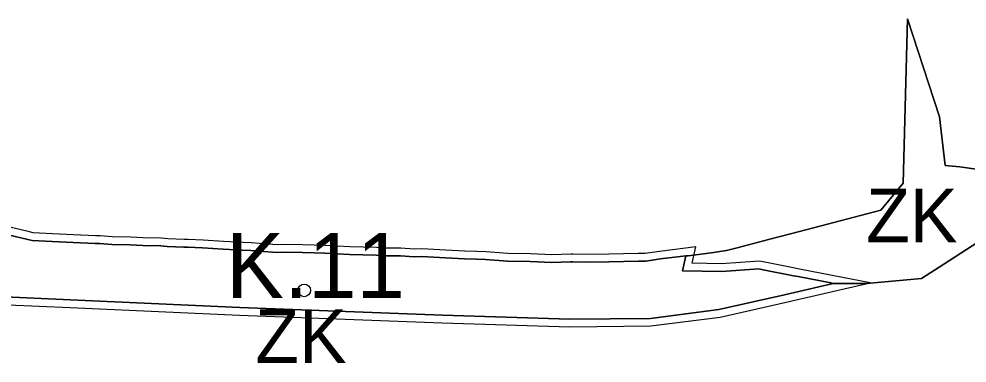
# Model space of a CAD drawing. Extents: x -555509 to -553005, y -1186756 to -1182560.
# Drawn here: x -555081.4 to -554833.4, y -1186291.9 to -1186202.1 of the extents above; entities that cross this region are included whole.
import ezdxf

# ---------------------------------------------------------------- set-up
doc = ezdxf.new("R2010")
doc.units = 0
for name, color, linetype in [('Level 46', 7, 'Continuous'), ('Level 56', 7, 'Continuous'), ('Level 59', 7, 'Continuous'), ('Level 63', 7, 'Continuous'), ('navrh_ZK', 7, 'Continuous'), ('OBRYS_PLOCH', 7, 'Continuous'), ('stav_AP', 7, 'Continuous'), ('stav_ZK', 7, 'Continuous')]:
    doc.layers.add(name, color=color, linetype=linetype)

msp = doc.modelspace()

# ---------------------------------------------------------------- linework, layer by layer
at = {"layer": 'Level 46'}
msp.add_circle((-555006.78, -1186272.95), 1.64, dxfattribs=at)
at = {"layer": 'Level 56'}
msp.add_lwpolyline([(-555092.41, -1186276.35), (-555068.02, -1186277.38), (-555023.74, -1186279.43), (-554970.68, -1186281.4), (-554937.3, -1186282.48), (-554916.11, -1186282.25), (-554897.96, -1186279.95), (-554880.77, -1186276.05), (-554858.76, -1186270.94), (-554868.68, -1186269.05), (-554877.26, -1186267.4), (-554878.46, -1186267.16), (-554886.36, -1186265.6), (-554887.72, -1186265.29), (-554897.64, -1186266.01), (-554905.34, -1186265.88), (-554904.39, -1186261.61), (-554913.89, -1186262.77), (-554917.63, -1186263.28), (-554919.43, -1186263.33), (-554927.14, -1186263.47), (-554932.26, -1186263.55), (-554936.49, -1186263.5), (-554937.09, -1186263.47), (-554942.03, -1186263.63), (-554947.61, -1186263.42), (-554953.57, -1186263.32), (-554959.24, -1186262.92), (-554961.6, -1186262.81), (-554964.74, -1186262.67), (-554969.75, -1186262.42), (-554976.05, -1186262.1), (-554978.04, -1186262.16), (-554981.52, -1186261.95), (-554986.17, -1186261.91), (-554987.88, -1186261.78), (-554994.82, -1186261.58), (-555001.28, -1186261.21), (-555004.17, -1186261.18), (-555007.2, -1186261.05), (-555012.39, -1186260.95), (-555013.86, -1186261.01), (-555018.52, -1186260.69), (-555020.66, -1186260.57), (-555022.78, -1186260.45), (-555027.86, -1186260.21), (-555033.24, -1186259.86), (-555037.13, -1186259.67), (-555038.17, -1186259.63), (-555042.48, -1186259.45), (-555045.1, -1186259.2), (-555047.35, -1186259.3), (-555052.24, -1186259.05), (-555057.03, -1186258.95), (-555060.12, -1186258.69), (-555061.37, -1186258.68), (-555067.15, -1186258.4), (-555072.6, -1186258.16), (-555077.64, -1186257.95), (-555078.59, -1186257.68), (-555085.64, -1186256)], dxfattribs=at)
at = {"layer": 'navrh_ZK'}
for p, q in [((-554907.83, -1186267.84), (-554906.96, -1186263.94)), ((-554897.58, -1186268.01), (-554907.83, -1186267.84)), ((-554887.87, -1186267.31), (-554897.58, -1186268.01)), ((-554886.77, -1186267.56), (-554887.87, -1186267.31)), ((-554878.85, -1186269.12), (-554886.77, -1186267.56)), ((-554877.64, -1186269.36), (-554878.85, -1186269.12)), ((-554869.06, -1186271.01), (-554877.64, -1186269.36)), ((-554868.43, -1186271.13), (-554869.06, -1186271.01)), ((-555089.85, -1186274.46), (-555067.93, -1186275.38))]:
    msp.add_line(p, q, dxfattribs=at)
for points in [[(-554906.96, -1186263.94), (-554913.63, -1186264.75), (-554917.47, -1186265.28), (-554919.39, -1186265.33), (-554927.11, -1186265.47), (-554932.26, -1186265.55), (-554936.56, -1186265.5), (-554937.11, -1186265.47), (-554942.03, -1186265.63), (-554947.66, -1186265.42), (-554953.66, -1186265.32), (-554959.36, -1186264.92), (-554961.69, -1186264.81), (-554964.83, -1186264.67), (-554969.85, -1186264.42), (-554976.07, -1186264.1), (-554978.07, -1186264.16), (-554981.59, -1186263.95), (-554986.25, -1186263.91), (-554987.98, -1186263.78), (-554994.91, -1186263.58), (-555001.35, -1186263.21), (-555004.22, -1186263.18), (-555007.26, -1186263.05), (-555012.37, -1186262.95), (-555013.89, -1186263.01), (-555018.64, -1186262.69), (-555020.77, -1186262.57), (-555022.88, -1186262.45), (-555027.97, -1186262.21), (-555033.35, -1186261.86), (-555037.22, -1186261.67), (-555038.25, -1186261.63), (-555042.62, -1186261.45), (-555045.15, -1186261.2), (-555047.35, -1186261.3), (-555052.31, -1186261.05), (-555057.13, -1186260.95), (-555060.21, -1186260.69), (-555061.43, -1186260.68), (-555067.24, -1186260.4), (-555072.69, -1186260.16), (-555077.96, -1186259.94), (-555079.09, -1186259.62), (-555084.2, -1186258.4)], [(-554937.28, -1186280.48), (-554916.25, -1186280.25), (-554898.31, -1186277.98), (-554881.21, -1186274.1), (-554868.43, -1186271.13)], [(-555067.93, -1186275.38), (-555023.66, -1186277.43), (-554970.61, -1186279.4), (-554937.28, -1186280.48)]]:
    msp.add_lwpolyline(points, dxfattribs=at)
at = {"layer": 'OBRYS_PLOCH'}
for p, q in [((-554849, -1186202.06), (-554850.12, -1186244.95)), ((-554850.12, -1186244.95), (-554849, -1186202.06)), ((-554840.62, -1186227.66), (-554849, -1186202.06)), ((-554849, -1186202.06), (-554840.62, -1186227.66)), ((-554839.16, -1186240.36), (-554840.62, -1186227.66)), ((-554840.62, -1186227.66), (-554839.16, -1186240.36)), ((-554835.28, -1186240.65), (-554839.16, -1186240.36)), ((-554839.16, -1186240.36), (-554835.28, -1186240.65)), ((-554830.46, -1186241.38), (-554835.28, -1186240.65)), ((-554835.28, -1186240.65), (-554830.46, -1186241.38)), ((-554850.12, -1186244.95), (-554855.96, -1186252.02)), ((-554855.96, -1186252.02), (-554850.12, -1186244.95)), ((-554855.96, -1186252.02), (-554869.97, -1186255.68)), ((-554869.97, -1186255.68), (-554855.96, -1186252.02)), ((-554869.97, -1186255.68), (-554877.27, -1186257.56)), ((-554877.27, -1186257.56), (-554869.97, -1186255.68)), ((-555079.09, -1186259.62), (-555084.2, -1186258.4)), ((-555084.2, -1186258.4), (-555079.09, -1186259.62)), ((-554877.27, -1186257.56), (-554885.02, -1186259.59)), ((-554885.02, -1186259.59), (-554877.27, -1186257.56)), ((-555077.96, -1186259.94), (-555079.09, -1186259.62)), ((-555079.09, -1186259.62), (-555077.96, -1186259.94)), ((-555072.69, -1186260.16), (-555077.96, -1186259.94)), ((-555077.96, -1186259.94), (-555072.69, -1186260.16)), ((-555067.24, -1186260.4), (-555072.69, -1186260.16)), ((-555061.43, -1186260.68), (-555067.24, -1186260.4)), ((-555060.21, -1186260.69), (-555061.43, -1186260.68)), ((-555061.43, -1186260.68), (-555060.21, -1186260.69)), ((-555060.21, -1186260.69), (-555057.13, -1186260.95)), ((-554885.02, -1186259.59), (-554893.59, -1186261.84)), ((-554893.59, -1186261.84), (-554885.02, -1186259.59)), ((-554839.51, -1186266.06), (-554829.17, -1186259.42)), ((-554829.17, -1186259.42), (-554839.51, -1186266.06)), ((-555045.15, -1186261.2), (-555047.35, -1186261.3)), ((-555047.35, -1186261.3), (-555045.15, -1186261.2)), ((-555045.15, -1186261.2), (-555042.62, -1186261.45)), ((-555042.62, -1186261.45), (-555038.25, -1186261.63)), ((-555038.25, -1186261.63), (-555037.22, -1186261.67)), ((-555037.22, -1186261.67), (-555033.35, -1186261.86)), ((-555022.88, -1186262.45), (-555027.97, -1186262.21)), ((-555020.77, -1186262.57), (-555022.88, -1186262.45)), ((-555022.88, -1186262.45), (-555020.77, -1186262.57)), ((-555018.64, -1186262.69), (-555020.77, -1186262.57)), ((-555020.77, -1186262.57), (-555018.64, -1186262.69)), ((-555013.89, -1186263.01), (-555018.64, -1186262.69)), ((-555018.64, -1186262.69), (-555013.89, -1186263.01)), ((-555012.37, -1186262.95), (-555013.89, -1186263.01)), ((-555013.89, -1186263.01), (-555012.37, -1186262.95)), ((-555007.26, -1186263.05), (-555012.37, -1186262.95)), ((-555012.37, -1186262.95), (-555007.26, -1186263.05)), ((-555007.26, -1186263.05), (-555004.22, -1186263.18)), ((-555004.22, -1186263.18), (-555001.35, -1186263.21)), ((-554994.91, -1186263.58), (-555001.35, -1186263.21)), ((-554900.36, -1186263.12), (-554906.34, -1186263.88)), ((-554906.34, -1186263.88), (-554900.36, -1186263.12)), ((-554896.34, -1186262.51), (-554900.36, -1186263.12)), ((-554900.36, -1186263.12), (-554896.34, -1186262.51)), ((-554893.59, -1186261.84), (-554896.34, -1186262.51)), ((-554896.34, -1186262.51), (-554893.59, -1186261.84)), ((-554987.98, -1186263.78), (-554994.91, -1186263.58)), ((-554986.25, -1186263.91), (-554987.98, -1186263.78)), ((-554987.98, -1186263.78), (-554986.25, -1186263.91)), ((-554981.59, -1186263.95), (-554986.25, -1186263.91)), ((-554986.25, -1186263.91), (-554981.59, -1186263.95)), ((-554981.59, -1186263.95), (-554978.07, -1186264.16)), ((-554978.07, -1186264.16), (-554976.07, -1186264.1)), ((-554976.07, -1186264.1), (-554969.85, -1186264.42)), ((-554969.85, -1186264.42), (-554964.83, -1186264.67)), ((-554961.69, -1186264.81), (-554964.83, -1186264.67)), ((-554964.83, -1186264.67), (-554961.69, -1186264.81)), ((-554959.36, -1186264.92), (-554961.69, -1186264.81)), ((-554961.69, -1186264.81), (-554959.36, -1186264.92)), ((-554953.66, -1186265.32), (-554959.36, -1186264.92)), ((-554947.66, -1186265.42), (-554953.66, -1186265.32)), ((-554942.03, -1186265.63), (-554947.66, -1186265.42)), ((-554947.66, -1186265.42), (-554942.03, -1186265.63)), ((-554937.11, -1186265.47), (-554942.03, -1186265.63)), ((-554942.03, -1186265.63), (-554937.11, -1186265.47)), ((-554936.56, -1186265.5), (-554937.11, -1186265.47)), ((-554937.11, -1186265.47), (-554936.56, -1186265.5)), ((-554919.39, -1186265.33), (-554927.11, -1186265.47)), ((-554927.11, -1186265.47), (-554919.39, -1186265.33)), ((-554917.47, -1186265.28), (-554919.39, -1186265.33)), ((-554919.39, -1186265.33), (-554917.47, -1186265.28)), ((-554913.63, -1186264.75), (-554917.47, -1186265.28)), ((-554906.96, -1186263.94), (-554913.63, -1186264.75)), ((-554906.96, -1186263.94), (-554907.83, -1186267.84)), ((-554907.83, -1186267.84), (-554906.96, -1186263.94)), ((-554907.83, -1186267.84), (-554906.96, -1186263.94)), ((-554906.34, -1186263.88), (-554906.96, -1186263.94)), ((-554906.96, -1186263.94), (-554906.34, -1186263.88)), ((-554907.83, -1186267.84), (-554897.58, -1186268.01)), ((-554897.58, -1186268.01), (-554907.83, -1186267.84)), ((-554897.58, -1186268.01), (-554907.83, -1186267.84)), ((-554897.58, -1186268.01), (-554887.87, -1186267.31)), ((-554887.87, -1186267.31), (-554897.58, -1186268.01)), ((-554887.87, -1186267.31), (-554897.58, -1186268.01)), ((-554887.87, -1186267.31), (-554886.77, -1186267.56)), ((-554886.77, -1186267.56), (-554887.87, -1186267.31)), ((-554886.77, -1186267.56), (-554887.87, -1186267.31)), ((-554886.77, -1186267.56), (-554878.85, -1186269.12)), ((-554878.85, -1186269.12), (-554886.77, -1186267.56)), ((-554878.85, -1186269.12), (-554886.77, -1186267.56)), ((-554845.34, -1186269.8), (-554839.51, -1186266.06)), ((-554839.51, -1186266.06), (-554845.34, -1186269.8)), ((-554878.85, -1186269.12), (-554877.64, -1186269.36)), ((-554877.64, -1186269.36), (-554878.85, -1186269.12)), ((-554877.64, -1186269.36), (-554878.85, -1186269.12)), ((-554877.64, -1186269.36), (-554869.06, -1186271.01)), ((-554869.06, -1186271.01), (-554877.64, -1186269.36)), ((-554869.06, -1186271.01), (-554877.64, -1186269.36)), ((-554859.71, -1186271.15), (-554845.34, -1186269.8)), ((-554845.34, -1186269.8), (-554859.71, -1186271.15)), ((-554869.06, -1186271.01), (-554868.43, -1186271.13)), ((-554868.43, -1186271.13), (-554869.06, -1186271.01)), ((-554868.43, -1186271.13), (-554869.06, -1186271.01)), ((-554868.43, -1186271.13), (-554860.32, -1186271.15)), ((-554860.32, -1186271.15), (-554868.43, -1186271.13)), ((-554860.32, -1186271.15), (-554859.71, -1186271.15)), ((-554859.71, -1186271.15), (-554860.32, -1186271.15)), ((-555089.85, -1186274.46), (-555067.93, -1186275.38)), ((-555089.85, -1186274.46), (-555067.93, -1186275.38)), ((-555067.93, -1186275.38), (-555089.85, -1186274.46)), ((-555067.93, -1186275.38), (-555023.66, -1186277.43)), ((-555023.66, -1186277.43), (-555067.93, -1186275.38)), ((-555023.66, -1186277.43), (-554970.61, -1186279.4)), ((-554970.61, -1186279.4), (-555023.66, -1186277.43)), ((-554898.31, -1186277.98), (-554916.25, -1186280.25)), ((-554970.61, -1186279.4), (-554937.28, -1186280.48)), ((-554937.28, -1186280.48), (-554970.61, -1186279.4)), ((-554916.25, -1186280.25), (-554937.28, -1186280.48))]:
    msp.add_line(p, q, dxfattribs=at)
for points in [[(-554906.96, -1186263.94), (-554913.63, -1186264.75), (-554917.47, -1186265.28), (-554919.39, -1186265.33), (-554927.11, -1186265.47), (-554932.26, -1186265.55), (-554936.56, -1186265.5), (-554937.11, -1186265.47), (-554942.03, -1186265.63), (-554947.66, -1186265.42), (-554953.66, -1186265.32), (-554959.36, -1186264.92), (-554961.69, -1186264.81), (-554964.83, -1186264.67), (-554969.85, -1186264.42), (-554976.07, -1186264.1), (-554978.07, -1186264.16), (-554981.59, -1186263.95), (-554986.25, -1186263.91), (-554987.98, -1186263.78), (-554994.91, -1186263.58), (-555001.35, -1186263.21), (-555004.22, -1186263.18), (-555007.26, -1186263.05), (-555012.37, -1186262.95), (-555013.89, -1186263.01), (-555018.64, -1186262.69), (-555020.77, -1186262.57), (-555022.88, -1186262.45), (-555027.97, -1186262.21), (-555033.35, -1186261.86), (-555037.22, -1186261.67), (-555038.25, -1186261.63), (-555042.62, -1186261.45), (-555045.15, -1186261.2), (-555047.35, -1186261.3), (-555052.31, -1186261.05), (-555057.13, -1186260.95), (-555060.21, -1186260.69), (-555061.43, -1186260.68), (-555067.24, -1186260.4), (-555072.69, -1186260.16), (-555077.96, -1186259.94), (-555079.09, -1186259.62), (-555084.2, -1186258.4)], [(-555072.69, -1186260.16), (-555067.24, -1186260.4), (-555061.43, -1186260.68)], [(-555047.35, -1186261.3), (-555052.31, -1186261.05), (-555057.13, -1186260.95), (-555060.21, -1186260.69)], [(-555057.13, -1186260.95), (-555052.31, -1186261.05), (-555047.35, -1186261.3)], [(-555038.25, -1186261.63), (-555042.62, -1186261.45), (-555045.15, -1186261.2)], [(-555027.97, -1186262.21), (-555033.35, -1186261.86), (-555037.22, -1186261.67), (-555038.25, -1186261.63)], [(-555033.35, -1186261.86), (-555027.97, -1186262.21), (-555022.88, -1186262.45)], [(-555001.35, -1186263.21), (-555004.22, -1186263.18), (-555007.26, -1186263.05)], [(-555001.35, -1186263.21), (-554994.91, -1186263.58), (-554987.98, -1186263.78)], [(-554964.83, -1186264.67), (-554969.85, -1186264.42), (-554976.07, -1186264.1), (-554978.07, -1186264.16), (-554981.59, -1186263.95)], [(-554959.36, -1186264.92), (-554953.66, -1186265.32), (-554947.66, -1186265.42)], [(-554927.11, -1186265.47), (-554932.26, -1186265.55), (-554936.56, -1186265.5)], [(-554936.56, -1186265.5), (-554932.26, -1186265.55), (-554927.11, -1186265.47)], [(-554917.47, -1186265.28), (-554913.63, -1186264.75), (-554906.96, -1186263.94)], [(-554937.28, -1186280.48), (-554916.25, -1186280.25), (-554898.31, -1186277.98), (-554881.21, -1186274.1), (-554868.43, -1186271.13)], [(-554937.28, -1186280.48), (-554916.25, -1186280.25), (-554898.31, -1186277.98), (-554881.21, -1186274.1), (-554868.43, -1186271.13)], [(-554868.43, -1186271.13), (-554881.21, -1186274.1), (-554898.31, -1186277.98)], [(-555067.93, -1186275.38), (-555023.66, -1186277.43), (-554970.61, -1186279.4), (-554937.28, -1186280.48)]]:
    msp.add_lwpolyline(points, dxfattribs=at)
at = {"layer": 'stav_AP'}
for p, q in [((-554850.12, -1186244.95), (-554849, -1186202.06)), ((-554849, -1186202.06), (-554840.62, -1186227.66)), ((-554840.62, -1186227.66), (-554839.16, -1186240.36)), ((-554839.16, -1186240.36), (-554835.28, -1186240.65)), ((-554835.28, -1186240.65), (-554830.46, -1186241.38)), ((-554855.96, -1186252.02), (-554850.12, -1186244.95)), ((-554869.97, -1186255.68), (-554855.96, -1186252.02)), ((-554877.27, -1186257.56), (-554869.97, -1186255.68)), ((-554885.02, -1186259.59), (-554877.27, -1186257.56)), ((-555077.96, -1186259.94), (-555072.69, -1186260.16)), ((-555072.69, -1186260.16), (-555067.24, -1186260.4)), ((-554893.59, -1186261.84), (-554885.02, -1186259.59)), ((-554829.17, -1186259.42), (-554839.51, -1186266.06)), ((-555052.31, -1186261.05), (-555047.35, -1186261.3)), ((-555047.35, -1186261.3), (-555045.15, -1186261.2)), ((-555037.22, -1186261.67), (-555033.35, -1186261.86)), ((-555020.77, -1186262.57), (-555018.64, -1186262.69)), ((-555004.22, -1186263.18), (-555001.35, -1186263.21)), ((-555001.35, -1186263.21), (-554994.91, -1186263.58)), ((-554900.36, -1186263.12), (-554896.34, -1186262.51)), ((-554896.34, -1186262.51), (-554893.59, -1186261.84)), ((-554986.25, -1186263.91), (-554981.59, -1186263.95)), ((-554976.07, -1186264.1), (-554969.85, -1186264.42)), ((-554961.69, -1186264.81), (-554959.36, -1186264.92)), ((-554959.36, -1186264.92), (-554953.66, -1186265.32)), ((-554942.03, -1186265.63), (-554937.11, -1186265.47)), ((-554937.11, -1186265.47), (-554936.56, -1186265.5)), ((-554936.56, -1186265.5), (-554932.26, -1186265.55)), ((-554932.26, -1186265.55), (-554927.11, -1186265.47)), ((-554927.11, -1186265.47), (-554919.39, -1186265.33)), ((-554919.39, -1186265.33), (-554917.47, -1186265.28)), ((-554917.47, -1186265.28), (-554913.63, -1186264.75)), ((-554913.63, -1186264.75), (-554906.96, -1186263.94)), ((-554839.51, -1186266.06), (-554845.34, -1186269.8)), ((-554845.34, -1186269.8), (-554859.71, -1186271.15)), ((-554868.43, -1186271.13), (-554881.21, -1186274.1)), ((-554860.32, -1186271.15), (-554868.43, -1186271.13)), ((-554859.71, -1186271.15), (-554860.32, -1186271.15)), ((-555067.93, -1186275.38), (-555089.85, -1186274.46)), ((-555023.66, -1186277.43), (-555067.93, -1186275.38)), ((-554881.21, -1186274.1), (-554898.31, -1186277.98)), ((-554898.31, -1186277.98), (-554916.25, -1186280.25)), ((-554916.25, -1186280.25), (-554937.28, -1186280.48))]:
    msp.add_line(p, q, dxfattribs=at)
for points in [[(-555084.2, -1186258.4), (-555079.09, -1186259.62), (-555077.96, -1186259.94)], [(-555067.24, -1186260.4), (-555061.43, -1186260.68), (-555060.21, -1186260.69), (-555057.13, -1186260.95), (-555052.31, -1186261.05)], [(-555045.15, -1186261.2), (-555042.62, -1186261.45), (-555038.25, -1186261.63), (-555037.22, -1186261.67)], [(-555033.35, -1186261.86), (-555027.97, -1186262.21), (-555022.88, -1186262.45), (-555020.77, -1186262.57)], [(-555018.64, -1186262.69), (-555013.89, -1186263.01), (-555012.37, -1186262.95), (-555007.26, -1186263.05), (-555004.22, -1186263.18)], [(-554906.96, -1186263.94), (-554906.34, -1186263.88), (-554900.36, -1186263.12)], [(-554994.91, -1186263.58), (-554987.98, -1186263.78), (-554986.25, -1186263.91)], [(-554981.59, -1186263.95), (-554978.07, -1186264.16), (-554976.07, -1186264.1)], [(-554969.85, -1186264.42), (-554964.83, -1186264.67), (-554961.69, -1186264.81)], [(-554953.66, -1186265.32), (-554947.66, -1186265.42), (-554942.03, -1186265.63)], [(-554937.28, -1186280.48), (-554970.61, -1186279.4), (-555023.66, -1186277.43)]]:
    msp.add_lwpolyline(points, dxfattribs=at)
at = {"layer": 'stav_ZK'}
for p, q in [((-554849, -1186202.06), (-554850.12, -1186244.95)), ((-554840.62, -1186227.66), (-554849, -1186202.06)), ((-554839.16, -1186240.36), (-554840.62, -1186227.66)), ((-554835.28, -1186240.65), (-554839.16, -1186240.36)), ((-554830.46, -1186241.38), (-554835.28, -1186240.65)), ((-554850.12, -1186244.95), (-554855.96, -1186252.02)), ((-554855.96, -1186252.02), (-554869.97, -1186255.68)), ((-554869.97, -1186255.68), (-554877.27, -1186257.56)), ((-554877.27, -1186257.56), (-554885.02, -1186259.59)), ((-554885.02, -1186259.59), (-554893.59, -1186261.84)), ((-554839.51, -1186266.06), (-554829.17, -1186259.42)), ((-554900.36, -1186263.12), (-554906.34, -1186263.88)), ((-554896.34, -1186262.51), (-554900.36, -1186263.12)), ((-554893.59, -1186261.84), (-554896.34, -1186262.51)), ((-554906.96, -1186263.94), (-554907.83, -1186267.84)), ((-554906.34, -1186263.88), (-554906.96, -1186263.94)), ((-554907.83, -1186267.84), (-554897.58, -1186268.01)), ((-554897.58, -1186268.01), (-554887.87, -1186267.31)), ((-554887.87, -1186267.31), (-554886.77, -1186267.56)), ((-554886.77, -1186267.56), (-554878.85, -1186269.12)), ((-554845.34, -1186269.8), (-554839.51, -1186266.06)), ((-554878.85, -1186269.12), (-554877.64, -1186269.36)), ((-554877.64, -1186269.36), (-554869.06, -1186271.01)), ((-554859.71, -1186271.15), (-554845.34, -1186269.8)), ((-554869.06, -1186271.01), (-554868.43, -1186271.13)), ((-554868.43, -1186271.13), (-554860.32, -1186271.15)), ((-554860.32, -1186271.15), (-554859.71, -1186271.15))]:
    msp.add_line(p, q, dxfattribs=at)

# ---------------------------------------------------------------- texts
at = {"layer": 'Level 46'}
msp.add_text('K.11', height=17, dxfattribs=at).set_placement((-555027.23, -1186274.97))
at = {"layer": 'Level 59'}
msp.add_text('ZK', height=14, dxfattribs=at).set_placement((-554859.84, -1186260.42))
at = {"layer": 'Level 63'}
msp.add_text('ZK', height=14, dxfattribs=at).set_placement((-555019.58, -1186291.92))

doc.saveas('drawing.dxf')
